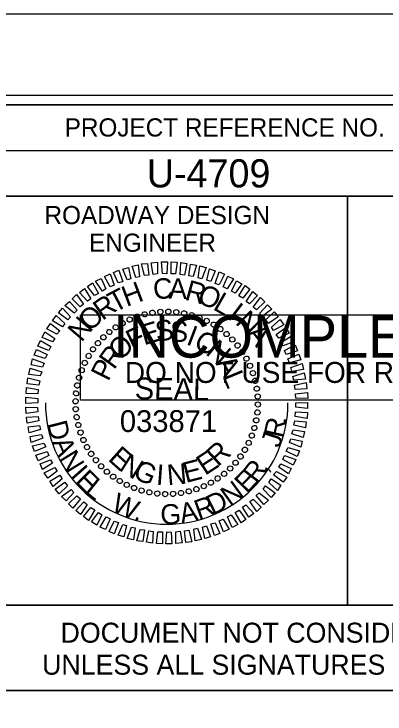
# Model space of a CAD drawing. Extents: x 1779926 to 1781610, y 620464 to 621564.
# Drawn here: x 1781401.2 to 1781503.2, y 621371.7 to 621564.2 of the extents above; entities that cross this region are included whole.
import ezdxf

# ---------------------------------------------------------------- set-up
doc = ezdxf.new("R2010")
doc.units = 0
for name, color, linetype in [('Old_Level_58', 7, 'Continuous'), ('Scratch_Level_0', 7, 'Continuous'), ('Sheet Cutting Line CELL', 7, 'Continuous'), ('Sheet Data Field CELL', 7, 'Continuous'), ('Sheet Plot Border Inside CELL', 7, 'Continuous'), ('Sheet Plot Border Outside CELL', 7, 'Continuous'), ('Sheet Professional Seal CELL', 7, 'Continuous'), ('Sheet Profile CELL', 7, 'Continuous'), ('Sheet Profile Grid Major CELL', 7, 'Continuous'), ('Sheet Profile Grid Minor CELL', 7, 'Continuous'), ('Sheet Sticker Exception Certification CELL', 7, 'Continuous'), ('Sheet Sticker Incomplete CELL', 7, 'Continuous')]:
    doc.layers.add(name, color=color, linetype=linetype)

msp = doc.modelspace()

# ---------------------------------------------------------------- linework, layer by layer
at = {"layer": 'Old_Level_58'}
msp.add_lwpolyline([(1781392.9, 621378.13), (1781592.95, 621378.13), (1781592.95, 621314.19), (1781392.9, 621314.19)], close=True, dxfattribs=at)
at = {"layer": 'Scratch_Level_0'}
msp.add_arc((1781443.19, 621457.25), 33.36, 180, 360, dxfattribs=at)
at = {"layer": 'Sheet Cutting Line CELL'}
msp.add_line((1781609.96, 621564.19), (1779925.96, 621564.19), dxfattribs=at)
at = {"layer": 'Sheet Plot Border Inside CELL'}
msp.add_lwpolyline([(1779938.96, 620486.64), (1781605.46, 620486.64), (1781605.46, 621541.74), (1779938.96, 621541.74)], close=True, dxfattribs=at)
at = {"layer": 'Sheet Plot Border Outside CELL'}
msp.add_lwpolyline([(1779925.96, 620464.19), (1781609.96, 620464.19), (1781609.96, 621564.19), (1779925.96, 621564.19)], close=True, dxfattribs=at)
at = {"layer": 'Sheet Professional Seal CELL'}
for p, q in [((1781434.99, 621481), (1781434.99, 621481)), ((1781437.09, 621481.6), (1781437.09, 621481.6)), ((1781439.29, 621482), (1781439.29, 621482)), ((1781441.44, 621482.3), (1781441.44, 621482.3)), ((1781443.64, 621482.35), (1781443.64, 621482.35)), ((1781445.84, 621482.2), (1781445.84, 621482.2)), ((1781447.99, 621481.85), (1781447.99, 621481.85)), ((1781450.09, 621481.4), (1781450.09, 621481.4)), ((1781452.19, 621480.7), (1781452.19, 621480.7)), ((1781431.04, 621479.2), (1781431.04, 621479.2)), ((1781432.99, 621480.2), (1781432.99, 621480.2)), ((1781454.19, 621479.8), (1781454.19, 621479.8)), ((1781456.14, 621478.8), (1781456.14, 621478.8)), ((1781427.39, 621476.8), (1781427.39, 621476.8)), ((1781429.14, 621478.05), (1781429.14, 621478.05)), ((1781457.94, 621477.55), (1781457.94, 621477.55)), ((1781425.74, 621475.3), (1781425.74, 621475.3)), ((1781459.69, 621476.2), (1781459.69, 621476.2)), ((1781461.24, 621474.7), (1781461.24, 621474.7)), ((1781424.24, 621473.75), (1781424.24, 621473.75)), ((1781462.74, 621473.05), (1781462.74, 621473.05)), ((1781422.89, 621472), (1781422.89, 621472)), ((1781463.99, 621471.3), (1781463.99, 621471.3)), ((1781421.64, 621470.2), (1781421.64, 621470.2)), ((1781465.14, 621469.4), (1781465.14, 621469.4)), ((1781420.64, 621468.25), (1781420.64, 621468.25)), ((1781466.14, 621467.45), (1781466.14, 621467.45)), ((1781419.74, 621466.25), (1781419.74, 621466.25)), ((1781466.94, 621465.45), (1781466.94, 621465.45)), ((1781419.04, 621464.15), (1781419.04, 621464.15)), ((1781467.54, 621463.35), (1781467.54, 621463.35)), ((1781418.59, 621462.05), (1781418.59, 621462.05)), ((1781418.24, 621459.9), (1781418.24, 621459.9)), ((1781467.94, 621461.15), (1781467.94, 621461.15)), ((1781418.09, 621457.7), (1781418.09, 621457.7)), ((1781468.24, 621459), (1781468.24, 621459)), ((1781418.14, 621455.5), (1781418.14, 621455.5)), ((1781443.19, 621457.25), (1781443.19, 621457.25)), ((1781468.29, 621456.8), (1781468.29, 621456.8)), ((1781468.14, 621454.6), (1781468.14, 621454.6)), ((1781418.44, 621453.35), (1781418.44, 621453.35)), ((1781467.79, 621452.45), (1781467.79, 621452.45)), ((1781418.84, 621451.15), (1781418.84, 621451.15)), ((1781467.34, 621450.35), (1781467.34, 621450.35)), ((1781419.44, 621449.05), (1781419.44, 621449.05)), ((1781466.64, 621448.25), (1781466.64, 621448.25)), ((1781420.24, 621447.05), (1781420.24, 621447.05)), ((1781465.74, 621446.25), (1781465.74, 621446.25)), ((1781421.24, 621445.1), (1781421.24, 621445.1)), ((1781464.74, 621444.3), (1781464.74, 621444.3)), ((1781422.39, 621443.2), (1781422.39, 621443.2)), ((1781463.49, 621442.5), (1781463.49, 621442.5)), ((1781423.64, 621441.45), (1781423.64, 621441.45)), ((1781462.14, 621440.75), (1781462.14, 621440.75)), ((1781425.14, 621439.8), (1781425.14, 621439.8)), ((1781426.69, 621438.3), (1781426.69, 621438.3)), ((1781460.64, 621439.2), (1781460.64, 621439.2)), ((1781428.44, 621436.95), (1781428.44, 621436.95)), ((1781457.24, 621436.45), (1781457.24, 621436.45)), ((1781458.99, 621437.7), (1781458.99, 621437.7)), ((1781430.24, 621435.7), (1781430.24, 621435.7)), ((1781432.19, 621434.7), (1781432.19, 621434.7)), ((1781453.39, 621434.3), (1781453.39, 621434.3)), ((1781455.34, 621435.3), (1781455.34, 621435.3)), ((1781434.19, 621433.8), (1781434.19, 621433.8)), ((1781436.29, 621433.1), (1781436.29, 621433.1)), ((1781438.39, 621432.65), (1781438.39, 621432.65)), ((1781447.09, 621432.5), (1781447.09, 621432.5)), ((1781449.29, 621432.9), (1781449.29, 621432.9)), ((1781451.39, 621433.5), (1781451.39, 621433.5)), ((1781440.54, 621432.3), (1781440.54, 621432.3)), ((1781442.74, 621432.15), (1781442.74, 621432.15)), ((1781444.94, 621432.2), (1781444.94, 621432.2))]:
    msp.add_line(p, q, dxfattribs=at)
for points in [[(1781439.49, 621492.55), (1781438.94, 621495.75), (1781440.64, 621495.95), (1781440.69, 621492.7)], [(1781441.99, 621492.8), (1781441.74, 621496.05), (1781443.39, 621496), (1781443.19, 621492.75)], [(1781444.39, 621492.75), (1781444.39, 621496), (1781446.04, 621495.95), (1781445.59, 621492.7)], [(1781432.29, 621491.05), (1781431.14, 621494.05), (1781432.69, 621494.5), (1781433.34, 621491.4)], [(1781434.69, 621491.7), (1781433.64, 621494.85), (1781435.34, 621495.2), (1781435.74, 621491.95)], [(1781437.09, 621492.25), (1781436.29, 621495.45), (1781437.94, 621495.6), (1781438.29, 621492.4)], [(1781446.89, 621492.6), (1781447.09, 621495.85), (1781448.74, 621495.55), (1781448.09, 621492.4)], [(1781449.29, 621492.2), (1781449.74, 621495.4), (1781451.39, 621495.15), (1781450.49, 621492.05)], [(1781451.84, 621491.65), (1781452.34, 621494.9), (1781454.04, 621494.5), (1781452.89, 621491.4)], [(1781454.24, 621491), (1781454.99, 621494.1), (1781456.54, 621493.6), (1781455.29, 621490.65)], [(1781427.64, 621489.2), (1781426.04, 621492), (1781427.59, 621492.7), (1781428.74, 621489.65)], [(1781429.84, 621490.25), (1781428.54, 621493.15), (1781430.04, 621493.75), (1781431.09, 621490.55)], [(1781456.49, 621490.1), (1781457.64, 621493.25), (1781459.04, 621492.65), (1781457.64, 621489.75)], [(1781458.74, 621489.15), (1781459.99, 621492.1), (1781461.54, 621491.4), (1781459.84, 621488.6)], [(1781423.29, 621486.75), (1781421.44, 621489.3), (1781422.74, 621490.25), (1781424.39, 621487.35)], [(1781425.49, 621488), (1781423.64, 621490.7), (1781425.19, 621491.5), (1781426.44, 621488.6)], [(1781461.04, 621488), (1781462.39, 621490.85), (1781463.89, 621490), (1781461.99, 621487.4)], [(1781421.39, 621485.25), (1781419.24, 621487.65), (1781420.59, 621488.7), (1781422.34, 621485.9)], [(1781462.99, 621486.65), (1781464.74, 621489.55), (1781466.04, 621488.5), (1781464.09, 621486.05)], [(1781419.39, 621483.7), (1781417.19, 621485.9), (1781418.39, 621487.1), (1781420.34, 621484.4)], [(1781465.04, 621485.15), (1781466.89, 621487.9), (1781468.19, 621486.8), (1781465.99, 621484.45)], [(1781417.74, 621481.95), (1781415.19, 621484), (1781416.44, 621485.15), (1781418.54, 621482.75)], [(1781466.94, 621483.6), (1781468.99, 621486.2), (1781470.19, 621485), (1781467.89, 621482.85)], [(1781415.99, 621480.05), (1781413.39, 621482), (1781414.49, 621483.3), (1781416.69, 621480.95)], [(1781468.74, 621481.85), (1781470.89, 621484.2), (1781472.09, 621483), (1781469.49, 621481.05)], [(1781414.49, 621478.15), (1781411.79, 621479.85), (1781412.74, 621481.3), (1781415.14, 621479.1)], [(1781470.49, 621480.05), (1781472.79, 621482.3), (1781473.84, 621480.95), (1781471.19, 621479.05)], [(1781412.99, 621476.15), (1781410.19, 621477.65), (1781411.19, 621479.05), (1781413.79, 621477.05)], [(1781471.99, 621478.1), (1781474.44, 621480.2), (1781475.39, 621478.75), (1781472.59, 621477.15)], [(1781411.79, 621474), (1781408.94, 621475.25), (1781409.69, 621476.8), (1781412.39, 621474.95)], [(1781473.29, 621476.05), (1781475.94, 621477.95), (1781476.89, 621476.45), (1781473.99, 621475.05)], [(1781474.59, 621473.85), (1781477.39, 621475.6), (1781478.04, 621474.05), (1781475.19, 621472.9)], [(1781410.79, 621471.7), (1781407.69, 621472.85), (1781408.44, 621474.4), (1781411.29, 621472.8)], [(1781475.59, 621471.7), (1781478.54, 621473.2), (1781479.19, 621471.6), (1781476.09, 621470.6)], [(1781409.79, 621469.5), (1781406.69, 621470.4), (1781407.34, 621471.95), (1781410.34, 621470.55)], [(1781409.04, 621467.1), (1781405.94, 621467.75), (1781406.29, 621469.4), (1781409.44, 621468.15)], [(1781476.49, 621469.35), (1781479.54, 621470.65), (1781480.09, 621469.1), (1781476.99, 621468.3)], [(1781477.29, 621466.95), (1781480.49, 621468.1), (1781480.79, 621466.45), (1781477.64, 621465.9)], [(1781408.39, 621464.7), (1781405.29, 621465.1), (1781405.64, 621466.8), (1781408.79, 621465.75)], [(1781477.89, 621464.55), (1781481.04, 621465.5), (1781481.34, 621463.8), (1781478.19, 621463.5)], [(1781407.99, 621462.15), (1781404.79, 621462.45), (1781404.99, 621464.15), (1781408.24, 621463.35)], [(1781407.74, 621459.75), (1781404.49, 621459.85), (1781404.59, 621461.5), (1781407.84, 621460.95)], [(1781478.34, 621462.15), (1781481.59, 621462.85), (1781481.74, 621461.15), (1781478.54, 621460.95)], [(1781478.64, 621459.75), (1781481.89, 621460.15), (1781481.99, 621458.45), (1781478.74, 621458.55)], [(1781407.69, 621457.25), (1781404.44, 621457.1), (1781404.44, 621458.8), (1781407.69, 621458.45)], [(1781478.69, 621457.25), (1781481.94, 621457.4), (1781481.94, 621455.7), (1781478.69, 621456.05)], [(1781407.74, 621454.75), (1781404.49, 621454.35), (1781404.39, 621456.05), (1781407.64, 621455.95)], [(1781408.04, 621452.35), (1781404.79, 621451.65), (1781404.64, 621453.35), (1781407.84, 621453.55)], [(1781478.64, 621454.75), (1781481.89, 621454.65), (1781481.79, 621453), (1781478.54, 621453.55)], [(1781478.39, 621452.35), (1781481.59, 621452.05), (1781481.39, 621450.35), (1781478.14, 621451.15)], [(1781408.49, 621449.95), (1781405.34, 621449), (1781405.04, 621450.7), (1781408.19, 621451)], [(1781477.99, 621449.8), (1781481.09, 621449.4), (1781480.74, 621447.7), (1781477.59, 621448.75)], [(1781409.09, 621447.55), (1781405.89, 621446.4), (1781405.59, 621448.05), (1781408.74, 621448.6)], [(1781409.89, 621445.15), (1781406.84, 621443.85), (1781406.29, 621445.4), (1781409.39, 621446.2)], [(1781477.34, 621447.4), (1781480.44, 621446.75), (1781480.09, 621445.1), (1781476.94, 621446.35)], [(1781410.79, 621442.8), (1781407.84, 621441.3), (1781407.19, 621442.9), (1781410.29, 621443.9)], [(1781476.59, 621445), (1781479.69, 621444.1), (1781479.04, 621442.55), (1781476.04, 621443.95)], [(1781475.59, 621442.8), (1781478.69, 621441.65), (1781477.94, 621440.1), (1781475.09, 621441.7)], [(1781411.79, 621440.65), (1781408.99, 621438.9), (1781408.34, 621440.45), (1781411.19, 621441.6)], [(1781474.59, 621440.5), (1781477.44, 621439.25), (1781476.69, 621437.7), (1781473.99, 621439.55)], [(1781413.09, 621438.45), (1781410.44, 621436.55), (1781409.49, 621438.05), (1781412.39, 621439.45)], [(1781473.39, 621438.35), (1781476.19, 621436.85), (1781475.19, 621435.45), (1781472.59, 621437.45)], [(1781414.39, 621436.4), (1781411.94, 621434.3), (1781410.99, 621435.75), (1781413.79, 621437.35)], [(1781471.89, 621436.35), (1781474.59, 621434.65), (1781473.64, 621433.2), (1781471.24, 621435.4)], [(1781415.89, 621434.45), (1781413.59, 621432.2), (1781412.54, 621433.55), (1781415.19, 621435.45)], [(1781470.39, 621434.45), (1781472.99, 621432.5), (1781471.89, 621431.2), (1781469.69, 621433.55)], [(1781417.64, 621432.65), (1781415.49, 621430.3), (1781414.29, 621431.5), (1781416.89, 621433.45)], [(1781468.64, 621432.55), (1781471.19, 621430.5), (1781469.94, 621429.35), (1781467.84, 621431.75)], [(1781419.44, 621430.9), (1781417.39, 621428.3), (1781416.19, 621429.5), (1781418.49, 621431.65)], [(1781466.99, 621430.8), (1781469.19, 621428.6), (1781467.99, 621427.4), (1781466.04, 621430.1)], [(1781421.34, 621429.35), (1781419.49, 621426.6), (1781418.19, 621427.7), (1781420.39, 621430.05)], [(1781464.99, 621429.25), (1781467.14, 621426.85), (1781465.79, 621425.8), (1781464.04, 621428.6)], [(1781423.39, 621427.85), (1781421.64, 621424.95), (1781420.34, 621426), (1781422.29, 621428.45)], [(1781425.34, 621426.5), (1781423.99, 621423.65), (1781422.49, 621424.5), (1781424.39, 621427.1)], [(1781463.09, 621427.75), (1781464.94, 621425.2), (1781463.64, 621424.25), (1781461.99, 621427.15)], [(1781427.64, 621425.35), (1781426.39, 621422.4), (1781424.84, 621423.1), (1781426.54, 621425.9)], [(1781429.89, 621424.4), (1781428.74, 621421.25), (1781427.34, 621421.85), (1781428.74, 621424.75)], [(1781458.74, 621425.3), (1781460.34, 621422.5), (1781458.79, 621421.8), (1781457.64, 621424.85)], [(1781460.89, 621426.5), (1781462.74, 621423.8), (1781461.19, 621423), (1781459.94, 621425.9)], [(1781432.14, 621423.5), (1781431.39, 621420.4), (1781429.84, 621420.9), (1781431.09, 621423.85)], [(1781434.54, 621422.85), (1781434.04, 621419.6), (1781432.34, 621420), (1781433.49, 621423.1)], [(1781451.69, 621422.8), (1781452.74, 621419.65), (1781451.04, 621419.3), (1781450.64, 621422.55)], [(1781454.09, 621423.45), (1781455.24, 621420.45), (1781453.69, 621420), (1781453.04, 621423.1)], [(1781456.54, 621424.25), (1781457.84, 621421.35), (1781456.34, 621420.75), (1781455.29, 621423.95)], [(1781437.09, 621422.3), (1781436.64, 621419.1), (1781434.99, 621419.35), (1781435.89, 621422.45)], [(1781439.49, 621421.9), (1781439.29, 621418.65), (1781437.64, 621418.95), (1781438.29, 621422.1)], [(1781441.99, 621421.75), (1781441.99, 621418.5), (1781440.34, 621418.55), (1781440.79, 621421.8)], [(1781444.39, 621421.7), (1781444.64, 621418.45), (1781442.99, 621418.5), (1781443.19, 621421.75)], [(1781446.89, 621421.95), (1781447.44, 621418.75), (1781445.74, 621418.55), (1781445.69, 621421.8)], [(1781449.29, 621422.25), (1781450.09, 621419.05), (1781448.44, 621418.9), (1781448.09, 621422.1)]]:
    msp.add_lwpolyline(points, close=True, dxfattribs=at)
for centre, major_axis in [((1781439.27, 621482.02), (-0.113, 0.711)), ((1781441.44, 621482.27), (-0.05, 0.718)), ((1781443.63, 621482.33), (0.013, 0.72)), ((1781445.82, 621482.19), (0.075, 0.716)), ((1781447.98, 621481.87), (0.137, 0.707)), ((1781432.99, 621480.16), (-0.293, 0.658)), ((1781435.03, 621480.96), (-0.234, 0.681)), ((1781437.13, 621481.59), (-0.174, 0.699)), ((1781450.11, 621481.36), (0.198, 0.692)), ((1781452.18, 621480.66), (0.258, 0.672)), ((1781454.19, 621479.79), (0.316, 0.647)), ((1781429.17, 621478.04), (-0.403, 0.597)), ((1781431.04, 621479.19), (-0.349, 0.63)), ((1781456.11, 621478.75), (0.371, 0.617)), ((1781427.41, 621476.74), (-0.453, 0.56)), ((1781457.94, 621477.54), (0.423, 0.582)), ((1781459.65, 621476.18), (0.472, 0.543)), ((1781425.77, 621475.29), (-0.5, 0.518)), ((1781461.24, 621474.67), (0.518, 0.5)), ((1781422.9, 621471.99), (-0.582, 0.423)), ((1781424.27, 621473.7), (-0.543, 0.472)), ((1781462.68, 621473.03), (0.56, 0.453)), ((1781421.7, 621470.17), (-0.617, 0.371)), ((1781463.99, 621471.27), (0.597, 0.403)), ((1781420.65, 621468.24), (-0.647, 0.316)), ((1781465.13, 621469.41), (0.63, 0.349)), ((1781419.78, 621466.24), (-0.672, 0.258)), ((1781466.11, 621467.45), (0.658, 0.293)), ((1781466.91, 621465.42), (0.681, 0.234)), ((1781419.09, 621464.16), (-0.692, 0.198)), ((1781467.53, 621463.32), (0.699, 0.174)), ((1781418.57, 621462.04), (-0.707, 0.137)), ((1781467.97, 621461.17), (0.711, 0.113)), ((1781418.25, 621459.87), (-0.716, 0.075)), ((1781468.21, 621459), (0.718, 0.05)), ((1781418.12, 621457.69), (-0.72, 0.013)), ((1781468.27, 621456.81), (0.72, -0.013)), ((1781418.18, 621455.5), (-0.718, -0.05)), ((1781418.42, 621453.33), (-0.711, -0.113)), ((1781468.14, 621454.63), (0.716, -0.075)), ((1781418.86, 621451.18), (-0.699, -0.174)), ((1781467.81, 621452.46), (0.707, -0.137)), ((1781419.48, 621449.08), (-0.681, -0.234)), ((1781467.3, 621450.34), (0.692, -0.198)), ((1781420.28, 621447.05), (-0.658, -0.293)), ((1781466.61, 621448.26), (0.672, -0.258)), ((1781421.26, 621445.09), (-0.63, -0.349)), ((1781465.74, 621446.26), (0.647, -0.316)), ((1781422.4, 621443.23), (-0.597, -0.403)), ((1781464.69, 621444.33), (0.617, -0.371)), ((1781423.7, 621441.47), (-0.56, -0.453)), ((1781463.48, 621442.51), (0.582, -0.423)), ((1781425.15, 621439.83), (-0.518, -0.5)), ((1781462.12, 621440.8), (0.543, -0.472)), ((1781426.74, 621438.32), (-0.472, -0.543)), ((1781458.98, 621437.76), (0.453, -0.56)), ((1781460.62, 621439.21), (0.5, -0.518)), ((1781428.45, 621436.96), (-0.423, -0.582)), ((1781430.28, 621435.75), (-0.371, -0.617)), ((1781457.22, 621436.46), (0.403, -0.597)), ((1781432.2, 621434.71), (-0.316, -0.647)), ((1781434.21, 621433.84), (-0.258, -0.672)), ((1781451.36, 621433.54), (0.234, -0.681)), ((1781453.39, 621434.34), (0.293, -0.658)), ((1781455.35, 621435.31), (0.349, -0.63)), ((1781436.28, 621433.14), (-0.198, -0.692)), ((1781438.41, 621432.63), (-0.137, -0.707)), ((1781440.57, 621432.31), (-0.075, -0.716)), ((1781442.76, 621432.17), (-0.013, -0.72)), ((1781444.94, 621432.23), (0.05, -0.718)), ((1781447.12, 621432.48), (0.113, -0.711)), ((1781449.26, 621432.92), (0.174, -0.699))]:
    msp.add_ellipse(centre, major_axis=major_axis, ratio=0.999708, dxfattribs=at)
at = {"layer": 'Sheet Profile CELL'}
for p, q in [((1781392.91, 621526.64), (1781592.96, 621526.64)), ((1781492.96, 621514.14), (1781492.96, 621401.69))]:
    msp.add_line(p, q, dxfattribs=at)
for points in [[(1781592.96, 621539.19), (1780092.96, 621539.19), (1780092.96, 620489.19), (1781592.96, 620489.19)], [(1781392.91, 621539.19), (1781592.96, 621539.19), (1781592.96, 621514.14), (1781392.91, 621514.14)], [(1781392.91, 621514.14), (1781492.96, 621514.14), (1781492.96, 621401.64), (1781392.91, 621401.64)], [(1781492.96, 621514.14), (1781592.96, 621514.14), (1781592.96, 621401.64), (1781492.96, 621401.64)]]:
    msp.add_lwpolyline(points, close=True, dxfattribs=at)
at = {"layer": 'Sheet Profile Grid Major CELL'}
msp.add_lwpolyline([(1781142.96, 621039.19), (1781192.96, 621039.19), (1781192.96, 621539.19), (1781242.96, 621539.19), (1781242.96, 621039.19), (1781292.96, 621039.19), (1781292.96, 621539.19), (1781342.96, 621539.19), (1781342.96, 621039.19), (1781392.96, 621039.19), (1781392.96, 621539.19), (1781419.26, 621539.19)], dxfattribs=at)
at = {"layer": 'Sheet Sticker Exception Certification CELL'}
for p, q in [((1781392.91, 621401.64), (1781592.95, 621401.64)), ((1781392.91, 621401.64), (1781592.95, 621401.64)), ((1781592.95, 621378.14), (1781392.91, 621378.14)), ((1781592.95, 621378.14), (1781392.91, 621378.14))]:
    msp.add_line(p, q, dxfattribs=at)
at = {"layer": 'Sheet Sticker Incomplete CELL'}
msp.add_lwpolyline([(1781419.48, 621457.99), (1781419.48, 621481.49), (1781566.48, 621481.49), (1781566.48, 621457.99)], close=True, dxfattribs=at)

# ---------------------------------------------------------------- texts
at = {"layer": 'Sheet Data Field CELL'}
msp.add_text('U-4709', height=7.75, dxfattribs=at).set_placement((1781437.72, 621516.5))
at = {"layer": 'Sheet Professional Seal CELL'}
for s, height, rotation, p in [('H', 5.64, 20.6195, (1781432.14, 621483.6)), ('C', 5.64, 6.2199, (1781439.74, 621485.6)), ('A', 5.64, 359.0203, (1781443.69, 621485.9)), ('R', 5.64, 344.6211, (1781447.89, 621485.7)), ('T', 5.64, 27.8198, (1781428.89, 621481.95)), ('O', 5.64, 337.4212, (1781451.24, 621484.95)), ('R', 5.64, 35.0205, (1781425.49, 621479.75)), ('L', 5.64, 330.2209, (1781455.64, 621483.1)), ('I', 5.64, 323.0201, (1781459.69, 621480.7)), ('O', 5.64, 42.2217, (1781422.04, 621476.65)), ('N', 5.64, 315.8189, (1781461.84, 621479.15)), ('N', 5.64, 49.4235, (1781419.74, 621473.75)), ('E', 5.64, 16.6111, (1781436.94, 621473.05)), ('S', 5.64, 7.2556, (1781440.39, 621474.1)), ('S', 5.64, 357.9004, (1781443.99, 621474.15)), ('F', 5.64, 25.967, (1781433.74, 621471.55)), ('I', 5.64, 339.1896, (1781448.29, 621473.45)), ('O', 5.64, 329.8335, (1781450.29, 621472.75)), ('A', 5.64, 308.6172, (1781464.79, 621476.2)), ('O', 5.64, 44.6812, (1781430.44, 621468.6)), ('N', 5.64, 320.4766, (1781453.64, 621470.75)), ('R', 5.64, 54.0397, (1781428.69, 621466.15)), ('P', 5.64, 63.3989, (1781427.09, 621462.95)), ('A', 5.64, 301.7603, (1781456.49, 621468.15)), ('L', 5.64, 292.4008, (1781458.44, 621464.7)), ('SEAL', 5.998, 359, (1781434.34, 621458.25)), ('R', 5.64, 42.4814, (1781457.29, 621439.5)), ('E', 5.64, 318.2769, (1781426.79, 621441.6)), ('E', 5.64, 33.1241, (1781453.74, 621437.15)), ('N', 5.64, 327.634, (1781429.79, 621438.9)), ('G', 5.64, 336.9902, (1781433.59, 621436.65)), ('I', 5.64, 355.7012, (1781440.14, 621434.75)), ('N', 5.64, 5.0564, (1781443.49, 621434.6)), ('E', 5.64, 14.4118, (1781448.44, 621435.2))]:
    msp.add_text(s, height=height, rotation=rotation, dxfattribs=at).set_placement(p)
at = {"layer": 'Sheet Profile CELL'}
for s, height, p in [('PROJECT REFERENCE NO.', 5.0001, (1781415.12, 621530.5)), ('ROADWAY DESIGN', 5.0001, (1781409.57, 621506.4)), ('ENGINEER', 5, (1781421.82, 621498.8))]:
    msp.add_text(s, height=height, dxfattribs=at).set_placement(p)
at = {"layer": 'Sheet Profile Grid Minor CELL'}
msp.add_text('033871', height=5.998, dxfattribs=at).set_placement((1781430.3, 621449.24))
for s, rotation, p in [('D', 284.2682, (1781410.2, 621451.61)), ('R', 77.3541, (1781475.17, 621447.35)), ('.', 84.2805, (1781476.13, 621451.28)), ('J', 72.4855, (1781474.21, 621444.67)), ('A', 293.4128, (1781411.52, 621446.44)), ('N', 301.5986, (1781413.38, 621442.04)), ('I', 311.5304, (1781416.45, 621437.12)), ('R', 52.3788, (1781468, 621434.77)), ('E', 315.0508, (1781417.74, 621435.52)), ('E', 45.7958, (1781465.25, 621432.08)), (',', 59.3052, (1781470.52, 621437.93)), ('L', 321.6338, (1781420.4, 621432.74)), ('N', 35.8641, (1781460.58, 621428.65)), ('W', 336.8891, (1781427.65, 621427.61)), ('D', 26.7195, (1781455.82, 621426.25)), ('R', 19.793, (1781451.99, 621424.96)), ('G', 1.6755, (1781441.51, 621423.82)), ('A', 11.6072, (1781447.3, 621424.03)), ('.', 348.4952, (1781433.93, 621425.09))]:
    msp.add_text(s, height=5.5, rotation=rotation, dxfattribs=at).set_placement(p)
at = {"layer": 'Sheet Sticker Exception Certification CELL'}
for s, p in [('DOCUMENT NOT CONSIDERED FINAL', (1781413.98, 621391.3)), ('DOCUMENT NOT CONSIDERED FINAL', (1781413.98, 621391.3)), ('UNLESS ALL SIGNATURES COMPLETED', (1781408.91, 621382.5)), ('UNLESS ALL SIGNATURES COMPLETED', (1781408.91, 621382.5))]:
    msp.add_text(s, height=5.5, dxfattribs=at).set_placement(p)
at = {"layer": 'Sheet Sticker Incomplete CELL'}
for s, height, p in [('INCOMPLETE PLANS', 11.52, (1781428.43, 621469.69)), ('DO NOT USE FOR R/W ACQUISITION', 5.76, (1781431.68, 621462.74))]:
    msp.add_text(s, height=height, dxfattribs=at).set_placement(p)

doc.saveas('drawing.dxf')
